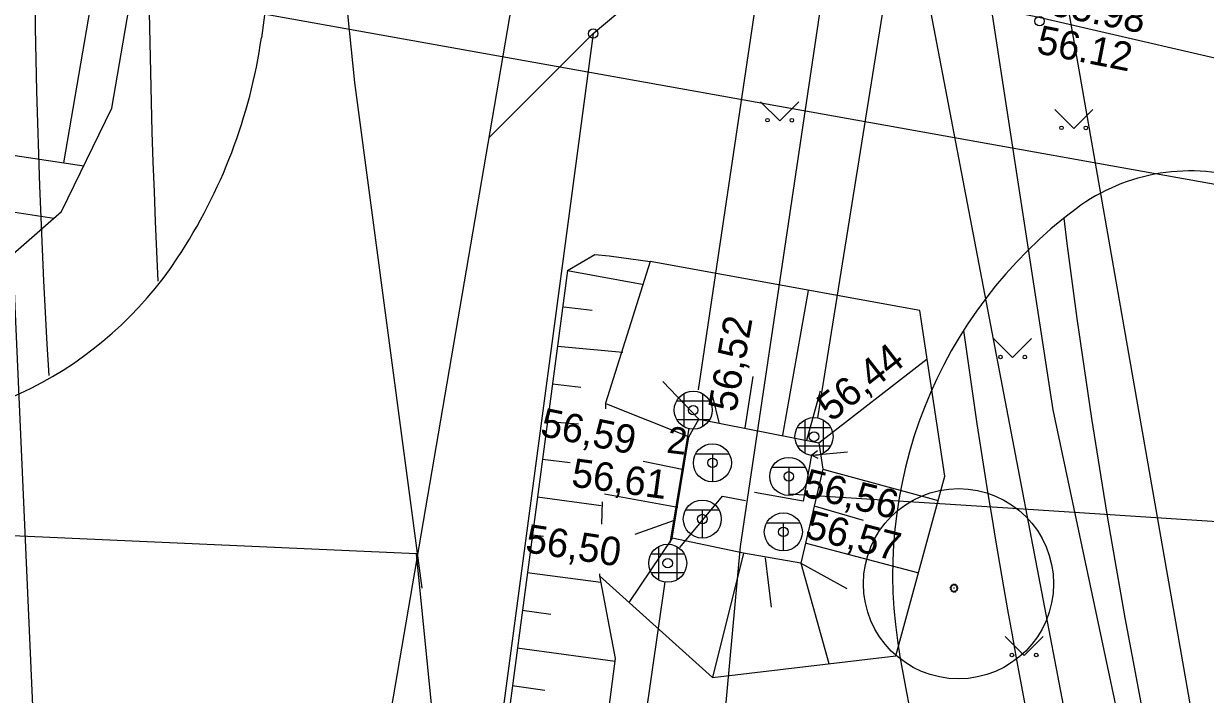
# Model space of a CAD drawing. Extents: x 9156 to 9809, y 2728 to 4000.
# Drawn here: x 9413.08 to 9444.15, y 3898.24 to 3915.86 of the extents above; entities that cross this region are included whole.
import ezdxf

# ---------------------------------------------------------------- set-up
doc = ezdxf.new("R2010")
doc.units = 0
for name, color, linetype in [('Level 12', 7, 'Continuous'), ('Level 14', 7, 'Continuous'), ('Level 15', 7, 'Continuous'), ('Level 17', 7, 'Continuous'), ('Level 18', 7, 'Continuous'), ('Level 41', 7, 'Continuous'), ('Level 54', 7, 'Continuous'), ('Level 56', 7, 'Continuous'), ('Level 59', 7, 'Continuous'), ('Level 6', 7, 'Continuous'), ('Level 7', 7, 'Continuous'), ('Level 9', 7, 'Continuous')]:
    doc.layers.add(name, color=color, linetype=linetype)

# ---------------------------------------------------------------- blocks, each defined once
blk = doc.blocks.new('VDREKA')
at = {"layer": 'Level 9'}
for p, q in [((-0.243, 0.437), (-0.243, -0.437)), ((0.243, 0.437), (0.243, -0.437)), ((-0.437, 0.243), (0.437, 0.243)), ((-0.437, -0.243), (0.437, -0.243))]:
    blk.add_line(p, q, dxfattribs=at)
blk.add_circle((0, 0), 0.5, dxfattribs=at)
blk = doc.blocks.new('VSOEKA')
at = {"layer": 'Level 6'}
for p, q in [((-0.438, 0.241), (0.439, 0.239)), ((0, 0.24), (0, -0.5))]:
    blk.add_line(p, q, dxfattribs=at)
blk.add_circle((0, 0), 0.5, dxfattribs=at)
blk = doc.blocks.new('MURU')
at = {"layer": 'Level 41'}
for p, q in [((-0.5, 0.5), (0, 0)), ((0, 0), (0.5, 0.5))]:
    blk.add_line(p, q, dxfattribs=at)
for centre in [(-0.32, 0.015), (0.32, 0.014)]:
    blk.add_circle(centre, 0.0466, dxfattribs=at)
blk = doc.blocks.new('KPUNKT')
at = {"layer": 'Level 59'}
blk.add_circle((0, 0), 0.125, dxfattribs=at)

msp = doc.modelspace()

# ---------------------------------------------------------------- linework, layer by layer
at = {"layer": 'Level 12'}
msp.add_line((9413.577, 3892.144), (9412.2, 3923.289), dxfattribs=at)
at = {"layer": 'Level 14'}
for p, q in [((9421.781, 3914.32), (9420.882, 3923.316)), ((9423.553, 3901.032), (9421.781, 3914.32)), ((9423.402, 3901.938), (9399.692, 3902.996)), ((9425.214, 3883.809), (9423.402, 3901.938))]:
    msp.add_line(p, q, dxfattribs=at)
at = {"layer": 'Level 15'}
for p, q in [((9440.149, 3905.714), (9438.337, 3917.498)), ((9446.039, 3877.916), (9440.149, 3905.714))]:
    msp.add_line(p, q, dxfattribs=at)
at = {"layer": 'Level 17'}
msp.add_line((9443.805, 3880.319), (9435.548, 3923.361), dxfattribs=at)
for centre, radius, start, end in [((9639.344, 3919.894), 226, 169.88959, 183.36818), ((9639.344, 3919.894), 223, 169.88959, 182.77512), ((9631.829, 3934.713), 192.9, 187.13653, 212.29226), ((9631.829, 3934.713), 195.9, 187.89598, 211.0202)]:
    msp.add_arc(centre, radius, start, end, dxfattribs=at)
at = {"layer": 'Level 18'}
msp.add_line((9419.474, 3916.59), (9419.328, 3915.491), dxfattribs=at)
for centre, radius, start, end in [((9405.309, 3917.521), 14.165, 326.5271, 351.7627), ((9443.739, 3906.993), 5, 15.7363, 126.7206), ((9447.925, 3901.382), 12, 126.7206, 190.2728), ((9408.783, 3915.224), 10, 266.7988, 326.5271), ((9631.829, 3934.713), 198.9, 190.27283, 207.99609)]:
    msp.add_arc(centre, radius, start, end, dxfattribs=at)
at = {"layer": 'Level 54'}
for p, q in [((9431.927, 3902.125), (9437.754, 3941.348)), ((9436.011, 3941.162), (9430.809, 3906.242)), ((9439.541, 3940.452), (9433.953, 3905.503)), ((9414.137, 3912.205), (9415.423, 3919.774)), ((9415.397, 3913.645), (9416.409, 3919.606)), ((9428.052, 3915.601), (9415.976, 3825.147)), ((9428.052, 3915.601), (9425.316, 3912.867)), ((9395.88, 3914.999), (9414.656, 3912.124)), ((9395.655, 3913.477), (9413.874, 3910.754)), ((9414.074, 3910.929), (9415.397, 3913.645)), ((9428.473, 3909.763), (9429.546, 3909.611)), ((9427.378, 3909.376), (9416.171, 3825.133)), ((9427.378, 3909.376), (9429.343, 3909.019)), ((9429.546, 3909.611), (9428.378, 3905.896)), ((9436.635, 3908.328), (9429.546, 3909.611)), ((9433.035, 3905.054), (9433.712, 3908.855)), ((9427.277, 3908.422), (9428.021, 3908.333)), ((9437.295, 3903.976), (9436.635, 3908.328)), ((9427.113, 3907.393), (9428.832, 3907.229)), ((9433.982, 3904.851), (9436.834, 3907.055)), ((9432.043, 3905.242), (9432.258, 3906.595)), ((9426.981, 3906.402), (9427.725, 3906.313)), ((9430.826, 3905.473), (9429.884, 3906.465)), ((9433.669, 3904.925), (9434.028, 3906.22)), ((9431.366, 3905.385), (9431.198, 3906.069)), ((9428.378, 3905.896), (9428.372, 3905.741)), ((9430.566, 3905.011), (9428.41, 3905.864)), ((9426.849, 3905.411), (9427.668, 3905.347)), ((9430.566, 3905.011), (9430.826, 3905.473)), ((9430.826, 3905.473), (9433.982, 3904.851)), ((9430.562, 3905.237), (9430.066, 3902.212)), ((9430.129, 3902.348), (9430.566, 3905.011)), ((9433.982, 3904.851), (9434.087, 3904.162)), ((9426.716, 3904.42), (9427.448, 3904.332)), ((9430.432, 3904.14), (9429.368, 3904.362)), ((9433.799, 3904.529), (9433.956, 3904.447)), ((9434.087, 3904.162), (9433.51, 3901.686)), ((9434.087, 3904.162), (9437.121, 3903.335)), ((9436.01, 3899.257), (9437.295, 3903.976)), ((9426.584, 3903.429), (9428.257, 3903.202)), ((9430.279, 3903.152), (9428.346, 3903.499)), ((9428.286, 3903.301), (9428.266, 3902.71)), ((9433.884, 3903.183), (9435.151, 3902.823)), ((9430.182, 3902.807), (9429.144, 3902.444)), ((9426.451, 3902.437), (9426.741, 3902.403)), ((9430.129, 3902.348), (9428.985, 3900.655)), ((9432.004, 3901.95), (9430.129, 3902.348)), ((9433.654, 3902.219), (9436.575, 3901.441)), ((9432.004, 3901.95), (9431.186, 3898.687)), ((9433.51, 3901.686), (9432.004, 3901.95)), ((9432.571, 3901.832), (9432.733, 3900.534)), ((9433.51, 3901.686), (9434.244, 3899.052)), ((9433.51, 3901.686), (9434.719, 3901.024)), ((9426.319, 3901.446), (9428.25, 3901.188)), ((9428.22, 3901.409), (9428.218, 3901.358)), ((9428.218, 3901.358), (9431.186, 3898.687)), ((9428.189, 3889.059), (9429.943, 3901.197)), ((9426.187, 3900.455), (9426.94, 3900.354)), ((9426.054, 3899.464), (9428.625, 3899.12)), ((9431.186, 3898.687), (9436.01, 3899.257)), ((9425.922, 3898.473), (9426.78, 3898.358))]:
    msp.add_line(p, q, dxfattribs=at)
for points in [[(9415.997, 3832.136), (9418.853, 3854.304), (9418.853, 3854.304), (9418.027, 3862.261), (9417.976, 3870.031), (9426.142, 3917.687)], [(9428.052, 3915.601), (9429.725, 3917.012), (9432.375, 3917.571), (9439.765, 3916.028), (9446.144, 3914.564), (9448.243, 3913.268), (9450.022, 3910.266), (9453.083, 3899.783), (9455.587, 3890.791), (9454.937, 3890.396), (9455.145, 3889.508), (9455.861, 3889.464), (9459.478, 3877.013), (9463.895, 3860.759), (9466.082, 3852.651)], [(9404.359, 3905.156), (9408.832, 3906.351), (9414.074, 3910.929)], [(9427.378, 3909.376), (9428.09, 3909.795), (9428.473, 3909.763)], [(9433.792, 3904.534), (9433.575, 3903.316), (9432.294, 3903.542)], [(9433.95, 3904.64), (9433.799, 3904.529), (9434.737, 3904.615)], [(9430.325, 3902.097), (9431.455, 3903.448), (9432.058, 3903.334)], [(9433.182, 3903.515), (9438.95, 3903.14), (9450.91, 3902.36), (9462.9, 3901.59), (9474.92, 3900.73), (9486.78, 3899.9), (9499.778, 3898.808)], [(9419.311, 3824.906), (9430.024, 3890.161), (9433.2, 3889.656), (9434.423, 3896.884), (9431.507, 3897.561), (9431.927, 3902.125)], [(9428.218, 3901.358), (9428.633, 3899.185), (9420.75, 3838.705)]]:
    msp.add_lwpolyline(points, dxfattribs=at)
for centre in [(9430.681, 3905.709), (9433.857, 3905.014), (9431.186, 3904.325), (9433.193, 3903.969), (9430.92, 3902.848), (9433.05, 3902.511), (9430.01, 3901.688), (9430.01, 3901.688)]:
    msp.add_circle(centre, 0.125, dxfattribs=at)
at = {"layer": 'Level 56'}
msp.add_line((9419.474, 3916.59), (9419.328, 3915.491), dxfattribs=at)
for centre, radius, start, end in [((9639.344, 3919.894), 226, 169.88959, 183.36818), ((9639.344, 3919.894), 223, 169.88959, 182.77512), ((9405.309, 3917.521), 14.165, 326.5271, 351.7627), ((9443.739, 3906.993), 5, 15.7363, 126.7206), ((9447.925, 3901.382), 12, 126.7206, 190.2728), ((9631.829, 3934.713), 192.9, 187.13653, 212.29226), ((9408.783, 3915.224), 10, 266.7988, 326.5271), ((9631.829, 3934.713), 195.9, 187.89598, 211.0202), ((9631.829, 3934.713), 198.9, 190.27283, 207.99609)]:
    msp.add_arc(centre, radius, start, end, dxfattribs=at)
at = {"layer": 'Level 6'}
msp.add_line((9769.71, 3853.431), (9292.325, 3938.851), dxfattribs=at)
at = {"layer": 'Level 7'}
msp.add_line((9439.242, 3923.641), (9446.918, 3879.882), dxfattribs=at)
at = {"layer": 'Level 9'}
for p, q in [((9437.461, 3901.045), (9437.439, 3901.048)), ((9437.439, 3901.019), (9437.461, 3901.023)), ((9437.447, 3901.075), (9437.468, 3901.067)), ((9437.467, 3901), (9437.448, 3900.991)), ((9437.48, 3901.085), (9437.463, 3901.099)), ((9437.463, 3900.968), (9437.479, 3900.982)), ((9437.484, 3901.118), (9437.496, 3901.099)), ((9437.496, 3900.967), (9437.484, 3900.949)), ((9437.517, 3901.109), (9437.51, 3901.13)), ((9437.51, 3900.937), (9437.516, 3900.958)), ((9437.549, 3901.032), (9437.528, 3901.032)), ((9437.539, 3900.954), (9437.538, 3900.932)), ((9437.539, 3901.134), (9437.539, 3901.112)), ((9437.539, 3901.022), (9437.539, 3901.043)), ((9437.56, 3901.109), (9437.566, 3901.13)), ((9437.567, 3900.936), (9437.561, 3900.957)), ((9437.581, 3900.966), (9437.593, 3900.948)), ((9437.593, 3901.118), (9437.582, 3901.099)), ((9437.598, 3901.085), (9437.615, 3901.099)), ((9437.616, 3900.968), (9437.599, 3900.983)), ((9437.63, 3901.075), (9437.611, 3901.065)), ((9437.611, 3901.001), (9437.631, 3900.992)), ((9437.617, 3901.044), (9437.638, 3901.048)), ((9437.639, 3901.02), (9437.617, 3901.023))]:
    msp.add_line(p, q, dxfattribs=at)
msp.add_circle((9437.656, 3901.15), 2.5, dxfattribs=at)
for radius, start, end in [(0.101, 155.3123, 171.7042), (0.101, 187.9671, 204.8625), (0.0788, 171.5431, 187.6203), (0.101, 122.8434, 139.0222), (0.101, 220.7122, 237.1166), (0.0788, 204.4529, 220.4774), (0.0788, 138.6432, 154.5795), (0.0788, 105.9559, 123.0564), (0.0788, 237.451, 253.0843), (0.101, 253.2952, 269.5718), (0.101, 90.0356, 106.342), (0.0788, 74.31, 90.043), (0.0788, 269.9461, 286.3473), (0.101, 57.6108, 74.1981), (0.101, 285.972, 302.5562), (0.0788, 302.254, 320.086), (0.0788, 41.2062, 56.7795), (0.0788, 8.0619, 24.0332), (0.0788, 336.0557, 352.7558), (0.101, 24.5394, 40.9852), (0.101, 319.7777, 336.0738), (0.101, 352.27, 8.583)]:
    msp.add_arc((9437.539, 3901.033), radius, start, end, dxfattribs=at)

# ---------------------------------------------------------------- block references
at = {"layer": 'Level 54'}
for name, p in [('KPUNKT', (9439.787, 3915.927)), ('KPUNKT', (9428.052, 3915.601)), ('MURU', (9432.954, 3913.31)), ('MURU', (9440.685, 3913.109)), ('MURU', (9439.079, 3907.089)), ('VDREKA', (9430.681, 3905.709)), ('VDREKA', (9433.857, 3905.014)), ('VSOEKA', (9431.186, 3904.325)), ('VSOEKA', (9433.193, 3903.969)), ('VSOEKA', (9430.92, 3902.848)), ('VSOEKA', (9433.05, 3902.511)), ('VDREKA', (9430.01, 3901.688)), ('MURU', (9439.38, 3899.262))]:
    msp.add_blockref(name, p, dxfattribs=at)

# ---------------------------------------------------------------- texts
for s, height, rotation, p in [('55.98', 0.75, 348.7829, (9440.033, 3916.091)), ('56.12', 0.75, 348.7829, (9439.678, 3915.091)), (' 56,52', 0.75, 79.9191, (9431.756, 3905.362)), (' 56,44', 0.75, 37.9993, (9434.091, 3905.211)), (' 56,59', 0.75, 348.514, (9426.356, 3905.095)), ('2', 0.7, 353.0718, (9429.96, 3904.596)), (' 56,61', 0.75, 352.3183, (9427.179, 3903.744)), (' 56,56', 0.75, 345.8108, (9433.255, 3903.525)), (' 56,57', 0.75, 345.3741, (9433.32, 3902.439)), (' 56,50', 0.75, 351.2318, (9425.966, 3902.023))]:
    msp.add_text(s, height=height, rotation=rotation, dxfattribs=at).set_placement(p)

doc.saveas('drawing.dxf')
